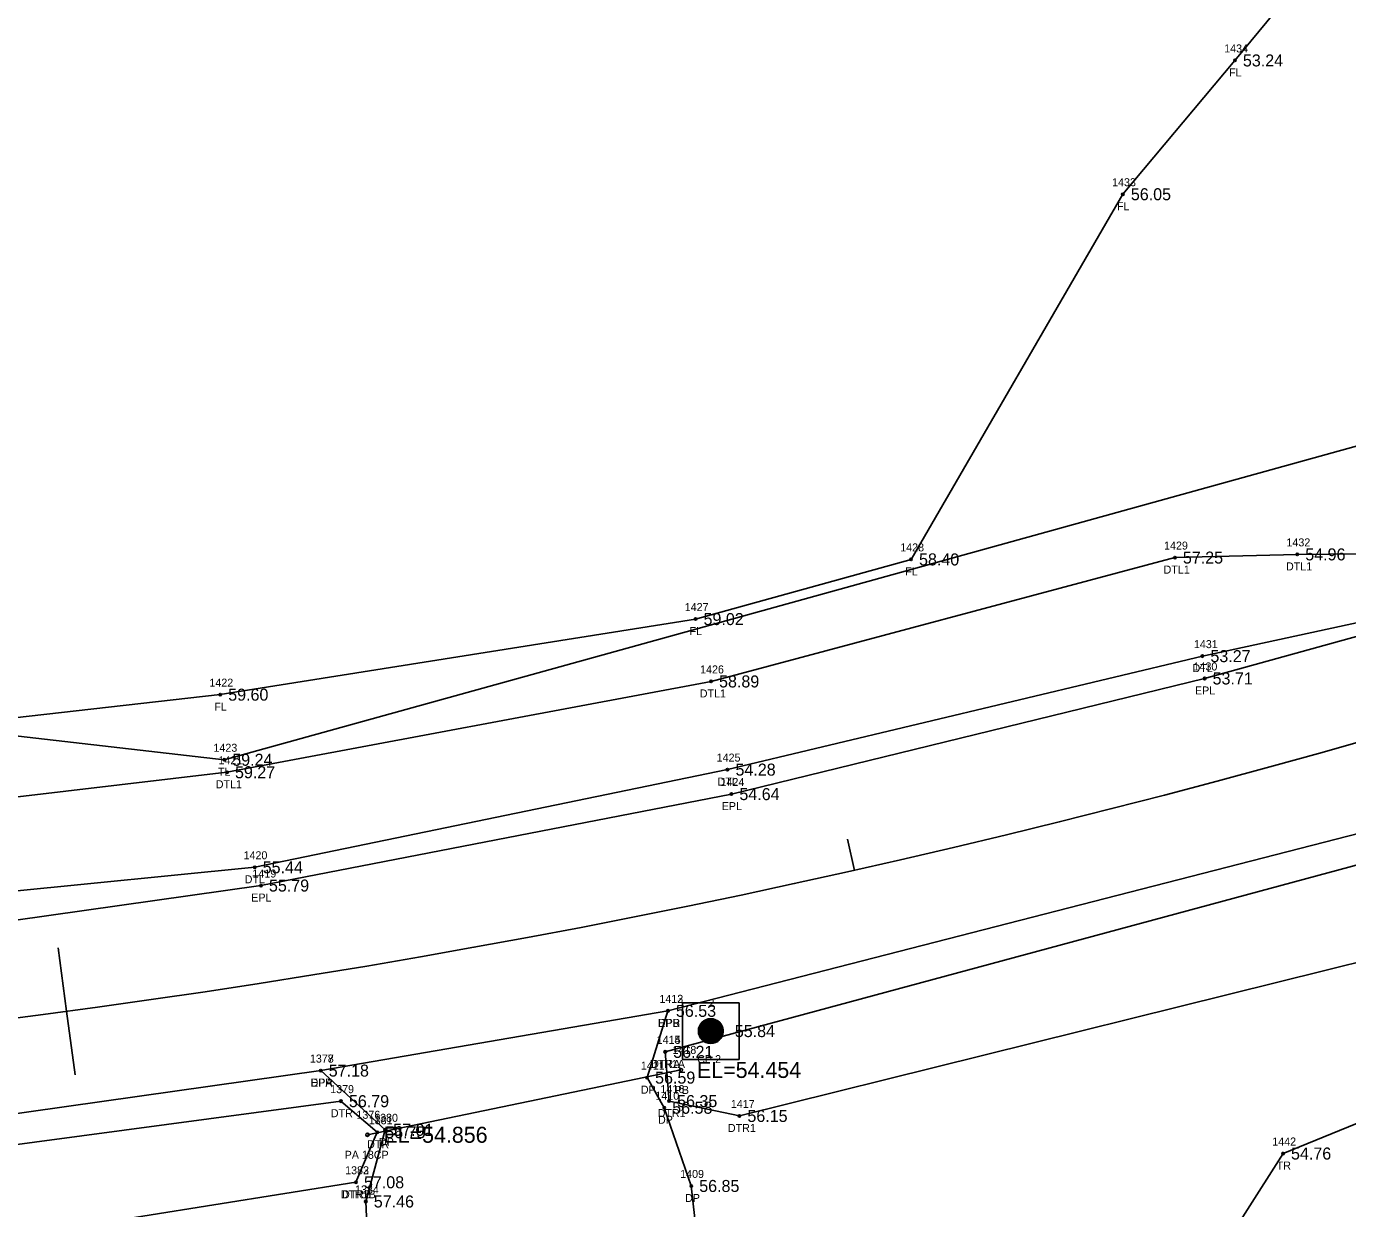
# Model space of a CAD drawing. Extents: x 2420113 to 2422887, y 845323 to 846653.
# Drawn here: x 2421383.1 to 2421548.1, y 845663.9 to 845811.6 of the extents above; entities that cross this region are included whole.
import ezdxf

# ---------------------------------------------------------------- set-up
doc = ezdxf.new("R2010")
doc.units = 0
for name, color, linetype in [('RD_EX_DR_Pipe', 7, 'Continuous'), ('RD_EX_DR_Pipe_txCode', 7, 'Continuous'), ('RD_EX_Driveway', 7, 'Continuous'), ('RD_EX_Driveway_txCode', 7, 'Continuous'), ('RD_EX_Fence_Other', 7, 'Continuous'), ('RD_EX_Fence_Other_txCode', 7, 'Continuous'), ('RD_EX_H2O', 7, 'Continuous'), ('RD_EX_H2O_txCode', 7, 'Continuous'), ('RD_EX_Road', 7, 'Continuous'), ('RD_EX_Road_txCode', 7, 'Continuous'), ('RD_EX_TX_Driveway_ELEV', 7, 'Continuous'), ('RD_EX_TX_Fence_Other_ELEV', 7, 'Continuous'), ('RD_EX_TX_H2O_ELEV', 7, 'Continuous'), ('RD_EX_TX_Road_ELEV', 7, 'Continuous'), ('RD_EX_TX_VEG_ELEV', 7, 'Continuous'), ('RD_EX_VEG', 7, 'Continuous'), ('RD_EX_VEG_txCode', 7, 'Continuous'), ('RD_HC_Cl', 7, 'Continuous'), ('RD_HC_Data_Tic', 7, 'Continuous'), ('RD_HC_Survey', 7, 'Continuous'), ('RD_HC_Survey_ELEV', 7, 'Continuous'), ('RD_HC_Survey_txCode', 7, 'Continuous'), ('RD_SMD_Locator', 7, 'Continuous'), ('RD_TX_Pipe_ElevEX', 7, 'Continuous')]:
    doc.layers.add(name, color=color, linetype=linetype)

msp = doc.modelspace()

# ---------------------------------------------------------------- linework, layer by layer
at = {"layer": 'RD_EX_DR_Pipe'}
msp.add_line((2421425.65, 845673.15), (2421464.82, 845681.25), dxfattribs=at)
at = {"layer": 'RD_EX_Driveway'}
for points in [[(2421479.56, 845590.02), (2421466.08, 845624.7), (2421464.21, 845636.68), (2421467.99, 845649.68), (2421466.1, 845666.76), (2421462.73, 845676.53), (2421460.59, 845680.29), (2421463.19, 845688.63)], [(2421419.82, 845681.17), (2421427.87, 845673.77), (2421425.45, 845664.82), (2421425.98, 845652.24), (2421431.45, 845642.48), (2421441.1, 845635.61), (2421450.11, 845631.38), (2421470.34, 845586.72)]]:
    msp.add_lwpolyline(points, dxfattribs=at)
at = {"layer": 'RD_EX_Fence_Other'}
msp.add_lwpolyline([(2420998.17, 846190.05), (2421002.97, 845999.17), (2421000.67, 845894.83), (2421000.75, 845767.39), (2421002.43, 845756.19), (2421040.55, 845726.54), (2421180.05, 845716.6), (2421291.96, 845715.08), (2421407.26, 845728.12), (2421466.64, 845737.56), (2421493.56, 845745.01), (2421520.02, 845790.62), (2421534.02, 845807.33), (2421566.2, 845846.23)], dxfattribs=at)
at = {"layer": 'RD_EX_H2O'}
for points in [[(2420975.55, 846190.58), (2420976.37, 846105.11), (2420974.31, 845997.82), (2420976.03, 845896.74), (2420974.59, 845794.18), (2420975.37, 845743.63), (2420984.12, 845720.99), (2420999.91, 845711.18), (2421116.7, 845699.77), (2421177.35, 845696.01), (2421236.57, 845694.11), (2421292.07, 845694.75), (2421349.67, 845700.43), (2421411.57, 845706.56), (2421470.63, 845718.76), (2421529.96, 845732.93), (2421551.14, 845737.51), (2421602.97, 845753.33), (2421656.85, 845776.48), (2421724.45, 845805.15), (2421739.21, 845812.56)], [(2421348.44, 845711.4), (2421408.11, 845718.43), (2421468.58, 845729.77), (2421526.52, 845745.24), (2421541.81, 845745.64), (2421549.75, 845745.7), (2421570.45, 845751.87), (2421591.88, 845757.66), (2421599.3, 845765.73), (2421650.04, 845787.07), (2421668.02, 845786.79), (2421719.15, 845813.59), (2421740.13, 845828.42)], [(2421462.85, 845683.51), (2421560.11, 845709.79), (2421615.97, 845726.65), (2421668.49, 845745.18), (2421738.54, 845774.52), (2421754.61, 845783.24)], [(2421462.85, 845683.51), (2421463.34, 845677.36), (2421472.12, 845675.5), (2421563.69, 845698.26), (2421619.71, 845715.72), (2421671.24, 845734.85), (2421744.95, 845763.45), (2421768.08, 845778.29)], [(2420681.02, 845707.72), (2420749.24, 845704.74), (2420794.5, 845700.07), (2420899.98, 845690.96), (2421017.54, 845678.31), (2421112.89, 845668.07), (2421174.6, 845666.39), (2421234.64, 845664.08), (2421293.38, 845665.28), (2421351.67, 845667.88), (2421422.34, 845677.35), (2421426.88, 845673.47), (2421424.22, 845667.22)], [(2420681.1, 845702.44), (2420748.92, 845698.41), (2420794.23, 845693.69), (2420899.45, 845684.25), (2421017.43, 845671.31), (2421111.87, 845660.39), (2421174.2, 845656.63), (2421235.06, 845654.38), (2421294.9, 845653.67), (2421353.19, 845655.89), (2421424.22, 845667.22)]]:
    msp.add_lwpolyline(points, dxfattribs=at)
at = {"layer": 'RD_EX_Road'}
for points in [[(2420388.28, 845680.39), (2420441.29, 845692.04), (2420492.62, 845700.7), (2420553.92, 845707.41), (2420607.69, 845710.85), (2420682.38, 845711.26), (2420749.44, 845707.27), (2420795.12, 845703.44), (2420900.28, 845693.42), (2421017.17, 845682.19), (2421113.9, 845672.97), (2421174.87, 845668.16), (2421234.59, 845666.13), (2421293, 845667.25), (2421351.24, 845671.5), (2421419.82, 845681.17), (2421463.19, 845688.63), (2421558.82, 845713.18), (2421614.57, 845730.45), (2421670.73, 845751.42), (2421735.61, 845780.5), (2421750.75, 845787.87), (2421744.67, 845798.22), (2421739.21, 845808.11)], [(2421350.22, 845695.49), (2421412.35, 845704.28), (2421471.12, 845715.7), (2421530.23, 845730.14), (2421551.47, 845736), (2421603.47, 845751.93), (2421659.09, 845772.43), (2421726.04, 845802.13), (2421739.21, 845808.11)]]:
    msp.add_lwpolyline(points, dxfattribs=at)
at = {"layer": 'RD_EX_VEG'}
for points in [[(2420990.17, 846190.24), (2420988, 845998.32), (2421000.67, 845894.83), (2421039.72, 845794.91), (2421064.26, 845723.75), (2421180.05, 845716.6), (2421345.47, 845727.16), (2421407.77, 845719.99), (2421650.04, 845787.07), (2421772.66, 845846.85), (2421772.66, 845846.85), (2421889.56, 845912.24), (2422060.37, 846045.26), (2422197.94, 846165.23), (2422281.92, 846227.58), (2422364.58, 846286.67), (2422339.46, 846334.5)], [(2421514.28, 845601.29), (2421515.71, 845632.65), (2421540.03, 845670.81), (2421822.4, 845786.03), (2421822.4, 845786.03), (2421928.63, 845815.98), (2422026.48, 845905.33), (2422114.13, 845963.57), (2422135.16, 845938.99)]]:
    msp.add_lwpolyline(points, dxfattribs=at)
at = {"layer": 'RD_HC_Cl'}
msp.add_arc((2421235.71, 846823.95), 1145.56, 264.46476, 308.21213, dxfattribs=at)
at = {"layer": 'RD_HC_Data_Tic'}
for p, q in [((2421486.49, 845706.17), (2421485.61, 845710.08)), ((2421388.08, 845688.57), (2421387.02, 845696.5)), ((2421388.08, 845688.57), (2421389.15, 845680.64))]:
    msp.add_line(p, q, dxfattribs=at)
at = {"layer": 'RD_HC_Survey'}
for p, q in [((2421467.23, 845685.27), (2421467.23, 845686.94)), ((2421467.28, 845685.19), (2421467.28, 845687.01)), ((2421467.33, 845685.13), (2421467.33, 845687.08)), ((2421467.38, 845685.07), (2421467.38, 845687.13)), ((2421467.43, 845685.02), (2421467.43, 845687.19)), ((2421467.48, 845684.97), (2421467.48, 845687.24)), ((2421467.53, 845684.92), (2421467.53, 845687.28)), ((2421467.58, 845684.88), (2421467.58, 845687.32)), ((2421467.63, 845684.84), (2421467.63, 845687.36)), ((2421467.68, 845684.81), (2421467.68, 845687.4)), ((2421467.73, 845684.78), (2421467.73, 845687.43)), ((2421467.78, 845684.75), (2421467.78, 845687.46)), ((2421467.83, 845684.72), (2421467.83, 845687.48)), ((2421467.88, 845684.7), (2421467.88, 845687.51)), ((2421467.93, 845684.67), (2421467.93, 845687.53)), ((2421467.98, 845684.65), (2421467.98, 845687.55)), ((2421468.03, 845684.63), (2421468.03, 845687.57)), ((2421468.08, 845684.62), (2421468.08, 845687.59)), ((2421468.13, 845684.6), (2421468.13, 845687.6)), ((2421468.18, 845684.59), (2421468.18, 845687.61)), ((2421468.23, 845684.58), (2421468.23, 845687.62)), ((2421468.28, 845684.57), (2421468.28, 845687.63)), ((2421468.33, 845684.56), (2421468.33, 845687.64)), ((2421468.38, 845684.56), (2421468.38, 845687.65)), ((2421468.43, 845684.55), (2421468.43, 845687.65)), ((2421468.48, 845684.55), (2421468.48, 845687.66)), ((2421468.53, 845684.55), (2421468.53, 845687.66)), ((2421468.58, 845684.55), (2421468.58, 845687.66)), ((2421468.63, 845684.55), (2421468.63, 845687.65)), ((2421468.68, 845684.55), (2421468.68, 845687.65)), ((2421468.73, 845684.56), (2421468.73, 845687.64)), ((2421468.78, 845684.57), (2421468.78, 845687.64)), ((2421468.83, 845684.57), (2421468.83, 845687.63)), ((2421468.88, 845684.58), (2421468.88, 845687.62)), ((2421468.93, 845684.6), (2421468.93, 845687.61)), ((2421468.98, 845684.61), (2421468.98, 845687.59)), ((2421469.03, 845684.63), (2421469.03, 845687.58)), ((2421469.08, 845684.64), (2421469.08, 845687.56)), ((2421469.13, 845684.66), (2421469.13, 845687.54)), ((2421469.18, 845684.68), (2421469.18, 845687.52)), ((2421469.23, 845684.71), (2421469.23, 845687.5)), ((2421469.28, 845684.73), (2421469.28, 845687.47)), ((2421469.33, 845684.76), (2421469.33, 845687.44)), ((2421469.38, 845684.79), (2421469.38, 845687.41)), ((2421469.43, 845684.83), (2421469.43, 845687.38)), ((2421469.48, 845684.86), (2421469.48, 845687.34)), ((2421469.53, 845684.9), (2421469.53, 845687.3)), ((2421469.58, 845684.94), (2421469.58, 845687.26)), ((2421469.63, 845684.99), (2421469.63, 845687.21)), ((2421469.68, 845685.04), (2421469.68, 845687.16)), ((2421469.73, 845685.1), (2421469.73, 845687.1)), ((2421469.78, 845685.16), (2421469.78, 845687.04)), ((2421469.83, 845685.23), (2421469.83, 845686.97)), ((2421469.88, 845685.31), (2421469.88, 845686.89)), ((2421467.03, 845685.74), (2421467.03, 845686.46)), ((2421467.08, 845685.57), (2421467.08, 845686.63)), ((2421467.13, 845685.45), (2421467.13, 845686.75)), ((2421467.18, 845685.35), (2421467.18, 845686.85)), ((2421469.93, 845685.4), (2421469.93, 845686.8)), ((2421469.98, 845685.51), (2421469.98, 845686.69)), ((2421470.03, 845685.65), (2421470.03, 845686.55)), ((2421470.08, 845685.88), (2421470.08, 845686.33))]:
    msp.add_line(p, q, dxfattribs=at)
msp.add_lwpolyline([(2421472.08, 845689.64), (2421465.01, 845689.64), (2421465.01, 845682.57), (2421472.08, 845682.57)], close=True, dxfattribs=at)
msp.add_circle((2421468.55, 845686.1), 1.55, dxfattribs=at)
at = {"layer": 'RD_SMD_Locator'}
for centre, radius in [((2421534.02, 845807.33), 0.15), ((2421520.02, 845790.62), 0.15), ((2421493.56, 845745.01), 0.15), ((2421526.52, 845745.24), 0.15), ((2421541.81, 845745.64), 0.15), ((2421466.64, 845737.56), 0.15), ((2421529.96, 845732.93), 0.15), ((2421468.58, 845729.77), 0.15), ((2421530.23, 845730.14), 0.15), ((2421407.26, 845728.12), 0.15), ((2421407.77, 845719.99), 0.15), ((2421408.11, 845718.43), 0.15), ((2421470.63, 845718.76), 0.15), ((2421471.12, 845715.7), 0.15), ((2421411.57, 845706.56), 0.15), ((2421412.35, 845704.28), 0.15), ((2421463.19, 845688.63), 0.15), ((2421463.19, 845688.63), 0.15), ((2421468.55, 845686.1), 0.15), ((2421462.85, 845683.51), 0.15), ((2421462.85, 845683.51), 0.15), ((2421419.82, 845681.17), 0.15), ((2421419.82, 845681.17), 0.15), ((2421460.59, 845680.29), 0.15), ((2421464.82, 845681.25), 0.2), ((2421422.34, 845677.35), 0.15), ((2421463.34, 845677.36), 0.15), ((2421462.73, 845676.53), 0.15), ((2421472.12, 845675.5), 0.15), ((2421427.87, 845673.77), 0.15), ((2421425.65, 845673.15), 0.2), ((2421426.88, 845673.47), 0.15), ((2421540.03, 845670.81), 0.15), ((2421424.22, 845667.22), 0.15), ((2421424.22, 845667.22), 0.15), ((2421466.1, 845666.76), 0.15), ((2421425.45, 845664.82), 0.15)]:
    msp.add_circle(centre, radius, dxfattribs=at)

# ---------------------------------------------------------------- texts
at = {"layer": 'RD_EX_DR_Pipe_txCode'}
for s, p in [('1418', (2421463.76, 845683.25)), ('PB', (2421464.04, 845678.25)), ('1376', (2421424.28, 845675.15)), ('PA 18CP', (2421422.81, 845670.15))]:
    msp.add_text(s, height=1, dxfattribs=at).set_placement(p)
at = {"layer": 'RD_EX_Driveway_txCode'}
for s, p in [('1412', (2421462.13, 845689.63)), ('DPB', (2421461.94, 845686.63)), ('1378', (2421418.47, 845682.17)), ('1411', (2421459.81, 845681.29)), ('DPA', (2421418.55, 845679.17)), ('DP', (2421459.81, 845678.29)), ('1410', (2421461.63, 845677.53)), ('1380', (2421426.49, 845674.77)), ('DP', (2421461.95, 845674.53)), ('DP', (2421427.09, 845671.77)), ('1409', (2421464.72, 845667.76)), ('1384', (2421424.1, 845665.82)), ('DP', (2421465.33, 845664.76))]:
    msp.add_text(s, height=1, dxfattribs=at).set_placement(p)
at = {"layer": 'RD_EX_Fence_Other_txCode'}
for s, p in [('1434', (2421532.68, 845808.33)), ('FL', (2421533.29, 845805.33)), ('1433', (2421518.68, 845791.62)), ('FL', (2421519.29, 845788.62)), ('1428', (2421492.21, 845746.01)), ('FL', (2421492.83, 845743.01)), ('1427', (2421465.29, 845738.56)), ('FL', (2421465.9, 845735.56)), ('1422', (2421405.91, 845729.12)), ('FL', (2421406.53, 845726.12))]:
    msp.add_text(s, height=1, dxfattribs=at).set_placement(p)
at = {"layer": 'RD_EX_H2O_txCode'}
for s, p in [('1429', (2421525.17, 845746.24)), ('1432', (2421540.46, 845746.64)), ('DTL1', (2421525.11, 845743.24)), ('DTL1', (2421540.4, 845743.64)), ('1431', (2421528.9, 845733.93)), ('1426', (2421467.21, 845730.77)), ('DTL', (2421528.72, 845730.93)), ('DTL1', (2421467.17, 845727.77)), ('1421', (2421407.05, 845719.43)), ('1425', (2421469.28, 845719.76)), ('DTL1', (2421406.71, 845716.43)), ('DTL', (2421469.39, 845716.76)), ('1420', (2421410.18, 845707.56)), ('DTL', (2421410.32, 845704.56)), ('1414', (2421461.79, 845684.51)), ('1415', (2421461.79, 845684.51)), ('DTR1A', (2421460.93, 845681.51)), ('DTRA', (2421461.1, 845681.51)), ('1379', (2421421, 845678.35)), ('1416', (2421462.26, 845678.36)), ('1417', (2421471.05, 845676.5)), ('DTR', (2421421.08, 845675.35)), ('1381', (2421425.82, 845674.47)), ('DTR1', (2421461.91, 845675.36)), ('DTR1', (2421470.68, 845673.5)), ('DTR', (2421425.61, 845671.47)), ('1382', (2421422.87, 845668.22)), ('1383', (2421422.87, 845668.22)), ('DTR1B', (2421422.31, 845665.22)), ('DTRB', (2421422.48, 845665.22))]:
    msp.add_text(s, height=1, dxfattribs=at).set_placement(p)
at = {"layer": 'RD_EX_Road_txCode'}
for s, p in [('1430', (2421528.85, 845731.14)), ('EPL', (2421529.03, 845728.14)), ('1424', (2421469.77, 845716.7)), ('EPL', (2421469.91, 845713.7)), ('1419', (2421411.29, 845705.28)), ('EPL', (2421411.14, 845702.28)), ('1413', (2421462.13, 845689.63)), ('EPR', (2421461.96, 845686.63)), ('1377', (2421418.47, 845682.17)), ('EPR', (2421418.59, 845679.17))]:
    msp.add_text(s, height=1, dxfattribs=at).set_placement(p)
at = {"layer": 'RD_EX_TX_Driveway_ELEV'}
for s, p in [('56.53', (2421464.19, 845687.88)), ('57.18', (2421420.82, 845680.42)), ('56.59', (2421461.59, 845679.54)), ('56.58', (2421463.73, 845675.78)), ('57.01', (2421428.87, 845673.02)), ('56.85', (2421467.1, 845666.01)), ('57.46', (2421426.45, 845664.07))]:
    msp.add_text(s, height=1.5, dxfattribs=at).set_placement(p)
at = {"layer": 'RD_EX_TX_Fence_Other_ELEV'}
for s, p in [('53.24', (2421535.02, 845806.58)), ('56.05', (2421521.02, 845789.87)), ('58.40', (2421494.56, 845744.26)), ('59.02', (2421467.64, 845736.81)), ('59.60', (2421408.26, 845727.37))]:
    msp.add_text(s, height=1.5, dxfattribs=at).set_placement(p)
at = {"layer": 'RD_EX_TX_H2O_ELEV'}
for s, p in [('54.96', (2421542.81, 845744.89)), ('57.25', (2421527.52, 845744.49)), ('53.27', (2421530.96, 845732.18)), ('58.89', (2421469.58, 845729.02)), ('59.27', (2421409.11, 845717.68)), ('54.28', (2421471.63, 845718.01)), ('55.44', (2421412.57, 845705.81)), ('56.21', (2421463.85, 845682.76)), ('56.21', (2421463.85, 845682.76)), ('56.79', (2421423.34, 845676.6)), ('56.35', (2421464.34, 845676.61)), ('56.15', (2421473.12, 845674.75)), ('56.75', (2421427.88, 845672.72)), ('57.08', (2421425.22, 845666.47)), ('57.08', (2421425.22, 845666.47))]:
    msp.add_text(s, height=1.5, dxfattribs=at).set_placement(p)
at = {"layer": 'RD_EX_TX_Road_ELEV'}
for s, p in [('53.71', (2421531.23, 845729.39)), ('54.64', (2421472.12, 845714.95)), ('55.79', (2421413.35, 845703.53)), ('56.53', (2421464.19, 845687.88)), ('57.18', (2421420.82, 845680.42))]:
    msp.add_text(s, height=1.5, dxfattribs=at).set_placement(p)
at = {"layer": 'RD_EX_TX_VEG_ELEV'}
for s, p in [('59.24', (2421408.77, 845719.24)), ('54.76', (2421541.03, 845670.06))]:
    msp.add_text(s, height=1.5, dxfattribs=at).set_placement(p)
at = {"layer": 'RD_EX_VEG_txCode'}
for s, p in [('1423', (2421406.42, 845720.99)), ('TL', (2421406.99, 845717.99)), ('1442', (2421538.69, 845671.81)), ('TR', (2421539.24, 845668.81))]:
    msp.add_text(s, height=1, dxfattribs=at).set_placement(p)
at = {"layer": 'RD_HC_Survey_ELEV'}
msp.add_text('55.84', height=1.5, dxfattribs=at).set_placement((2421471.55, 845685.35))
at = {"layer": 'RD_HC_Survey_txCode'}
for s, p in [('2', (2421468.26, 845689.1)), ('CP 2', (2421466.85, 845682.1))]:
    msp.add_text(s, height=1, dxfattribs=at).set_placement(p)
at = {"layer": 'RD_TX_Pipe_ElevEX'}
for s, p in [('EL=54.454', (2421466.82, 845680.25)), ('EL=54.856', (2421427.65, 845672.15))]:
    msp.add_text(s, height=2, dxfattribs=at).set_placement(p)

doc.saveas('drawing.dxf')
